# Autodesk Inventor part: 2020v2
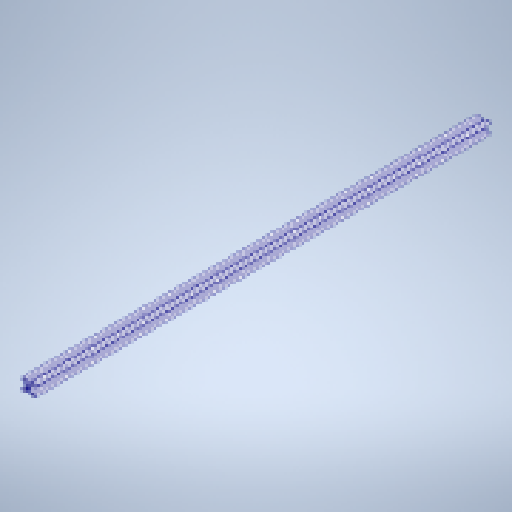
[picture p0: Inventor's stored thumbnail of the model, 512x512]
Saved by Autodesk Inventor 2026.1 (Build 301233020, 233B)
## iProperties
Created: 2024-09
Part Number: 2020v2
Material: Alluminio 6061
Document SubType Name: Modeling
Designer: hp
Density: 2.7 g/cm^3
Appearance: Default
Author: hp
Revision Number: ANY
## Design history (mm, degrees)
node "Solido1"
sketch "Sketch3"
  geometry: 2 further points
hole "Hole3" sketch "Sketch3" at (32.222, -3.027), (16.972, -3.027) diameter "d14" = 4.5; stored, may be unused: countersink angle "d18" = 90 deg, drill point angle "d20" = 0 deg; dims "d15" = 6, "d16" = 4, "d17" = 2, "d19" = 8
sketch "Sketch8"
  geometry: 2 further points
hole "Hole8" sketch "Sketch8" at (742, 3.053), (755, 3.053) diameter "d49" = 4.5; stored, may be unused: countersink angle "d53" = 90 deg, drill point angle "d55" = 0 deg; dims "d50" = 6, "d51" = 4, "d52" = 2, "d54" = 8
sketch "Sketch9"
  geometry: 2 further points
hole "Hole9" sketch "Sketch9" at (690.765, -3.027), (714.765, -3.027) diameter "d56" = 3.4; stored, may be unused: countersink angle "d60" = 90 deg, drill point angle "d62" = 0 deg; dims "d57" = 6, "d58" = 4, "d59" = 2, "d61" = 8
body "Solid1"
